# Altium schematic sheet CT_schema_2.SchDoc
size 276 x 169 mm
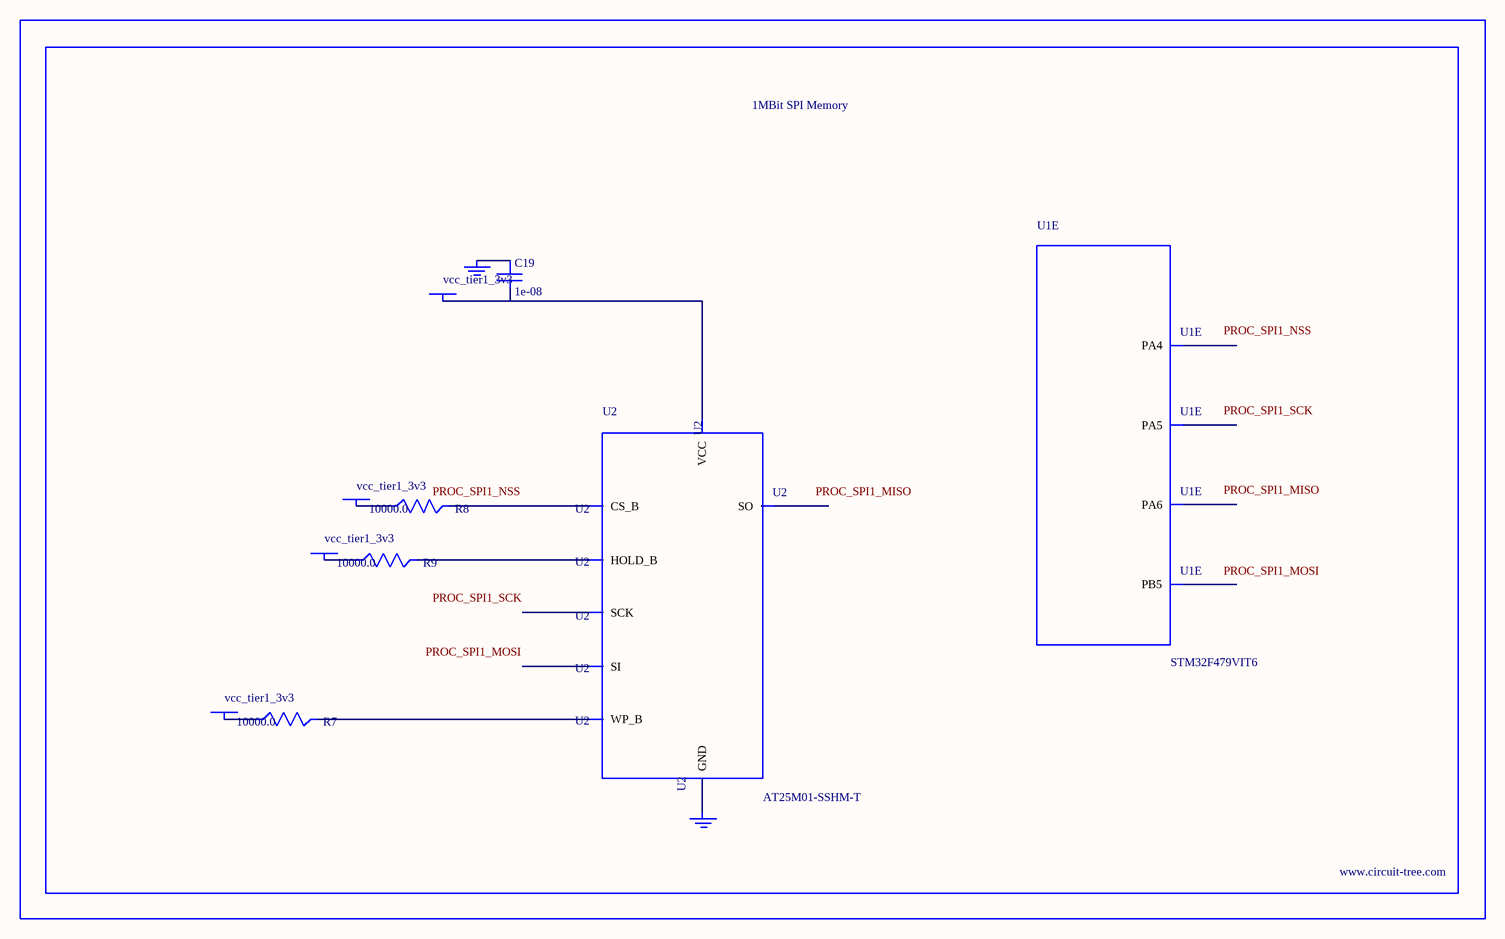
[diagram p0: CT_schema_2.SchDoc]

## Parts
BORDER1  (no value)
C19  1e-08  [C0402]
GND_INSTANCE_1_0  (no value)
GND_INSTANCE_1_1  (no value)
POWER_INSTANCE_1_0  vcc_tier1_3v3
POWER_INSTANCE_1_1  vcc_tier1_3v3
POWER_INSTANCE_1_2  vcc_tier1_3v3
POWER_INSTANCE_1_3  vcc_tier1_3v3
R7  10000.0  [R0603]
R8  10000.0  [R0603]
R9  10000.0  [R0603]
U1  STM32F479VIT6  [LQFP100]  (part E of 9)
U2  AT25M01-SSHM-T  [SOIC-8]

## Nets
NetC19_1: C19.1 GND_INSTANCE_1_0.0(GND)
NetC19_2: C19.2 POWER_INSTANCE_1_3.0(PWR) U2.8(VCC)
NetGND_INSTANCE_1_1_0: GND_INSTANCE_1_1.0(GND) U2.4(GND)
NetPOWER_INSTANCE_1_0_0: POWER_INSTANCE_1_0.0(PWR) R8.1
NetPOWER_INSTANCE_1_1_0: POWER_INSTANCE_1_1.0(PWR) R7.1
NetPOWER_INSTANCE_1_2_0: POWER_INSTANCE_1_2.0(PWR) R9.1
NetR7_2: R7.2 U2.3(WP_B)
NetR8_2: R8.2 U2.1(CS_B)
NetR9_2: R9.2 U2.7(HOLD_B)

Not connected (* = marked no-connect by the designer): U1 25(PA4) 26(PA5) 27(PA6) 94(PB5); U2 2(SO) 5(SI) 6(SCK)

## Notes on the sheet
- Labels drawn without touching a wire or pin: PROC_SPI1_MISO, PROC_SPI1_MOSI, PROC_SPI1_NSS, PROC_SPI1_SCK

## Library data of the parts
BORDER1 = BORDER_PAGE1
C19 = C0402C103K3RAC
GND_INSTANCE_1_0 GND_INSTANCE_1_1 = GND
POWER_INSTANCE_1_0-POWER_INSTANCE_1_3 = PWR
R7-R9 = RC0603JR-0710KL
